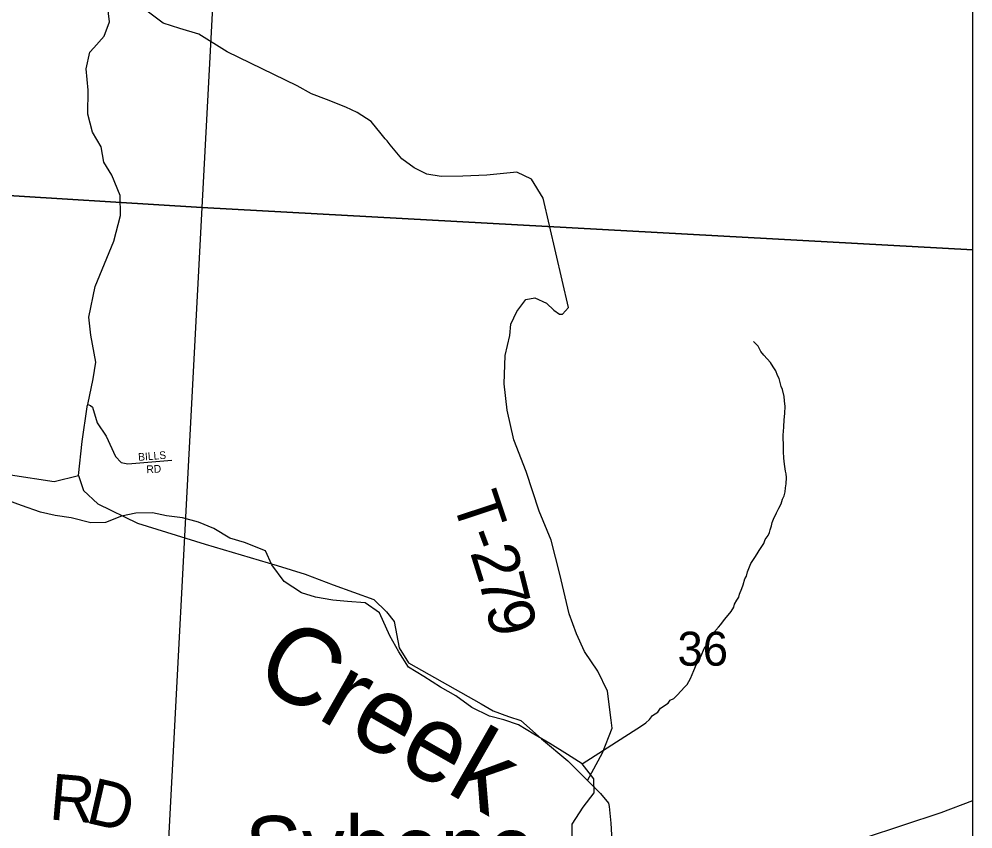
# Model space of a CAD drawing. Extents: x 1949938.81 to 1949945.61, y 152207.65 to 152214.09.
# Drawn here: x 1949944.431 to 1949945.607, y 152209.24 to 152210.239 of the extents above; entities that cross this region are included whole.
import ezdxf

# ---------------------------------------------------------------- set-up
doc = ezdxf.new("R2010")
doc.units = 0
for name, color, linetype in [('GM_X_County', 7, 'Continuous'), ('GM_X_County_Road', 7, 'Continuous'), ('GM_X_Minor_River', 7, 'Continuous'), ('GM_X_Minor_River_Text', 7, 'Continuous'), ('GM_X_Section', 7, 'Continuous'), ('GM_X_Section_Text', 7, 'Continuous'), ('GM_X_Township', 7, 'Continuous'), ('GM_X_Township_Road', 7, 'Continuous'), ('GM_X_Township_Road_Text', 7, 'Continuous'), ('GM_X_Township_ROW', 7, 'Continuous'), ('GM_X_Township_Subdivision', 7, 'Continuous'), ('GM_X_Township_Subdivision_Text', 7, 'Continuous'), ('GM_X_Unincorporated_Text', 7, 'Continuous'), ('GM_X_US_Route', 7, 'Continuous')]:
    doc.layers.add(name, color=color, linetype=linetype)

msp = doc.modelspace()

# ---------------------------------------------------------------- linework, layer by layer
at = {"layer": 'GM_X_County'}
msp.add_lwpolyline([(1949945.6069, 152208.8266), (1949945.6069, 152214.0874), (1949938.8069, 152214.0874), (1949938.8069, 152213.1813)], dxfattribs=at)
at = {"layer": 'GM_X_County_Road'}
msp.add_lwpolyline([(1949944.421, 152209.6768), (1949944.4748, 152209.6684), (1949944.5047, 152209.6757), (1949944.5108, 152209.6574), (1949944.5286, 152209.6411), (1949944.5774, 152209.6171), (1949944.6608, 152209.5912), (1949944.7494, 152209.5649), (1949944.7839, 152209.5543), (1949944.8183, 152209.5409), (1949944.8687, 152209.5231), (1949944.8843, 152209.5078), (1949944.8937, 152209.4957), (1949944.8998, 152209.4634), (1949944.9115, 152209.4451), (1949945.0009, 152209.3942), (1949945.0157, 152209.3858), (1949945.0346, 152209.3786), (1949945.0497, 152209.374), (1949945.0752, 152209.3511), (1949945.1076, 152209.3242), (1949945.1318, 152209.2997), (1949945.148, 152209.2838), (1949945.1578, 152209.2717), (1949945.1585, 152209.2678), (1949945.1608, 152209.2471), (1949945.1655, 152209.1604)], dxfattribs=at)
at = {"layer": 'GM_X_Minor_River'}
for points in [[(1949945.1253, 152209.3203), (1949945.1985, 152209.3674), (1949945.2039, 152209.3708), (1949945.2081, 152209.3749), (1949945.212, 152209.3801), (1949945.2185, 152209.3842), (1949945.222, 152209.3891), (1949945.2312, 152209.395), (1949945.2339, 152209.3987), (1949945.2381, 152209.401), (1949945.2424, 152209.4051), (1949945.2474, 152209.4103), (1949945.2516, 152209.4148), (1949945.2547, 152209.4182), (1949945.259, 152209.4257), (1949945.263, 152209.4355), (1949945.2661, 152209.4434), (1949945.2697, 152209.4491), (1949945.272, 152209.4536), (1949945.2756, 152209.4626), (1949945.2787, 152209.4664), (1949945.2822, 152209.4747), (1949945.2869, 152209.4796), (1949945.29, 152209.4852), (1949945.2935, 152209.489), (1949945.2962, 152209.4923), (1949945.3008, 152209.4983), (1949945.3051, 152209.5036), (1949945.3089, 152209.5081), (1949945.3121, 152209.5137), (1949945.3129, 152209.5171), (1949945.316, 152209.522), (1949945.3183, 152209.5258), (1949945.3192, 152209.5296), (1949945.3219, 152209.5364), (1949945.3239, 152209.5413), (1949945.3259, 152209.5485), (1949945.3279, 152209.5518), (1949945.3291, 152209.5571), (1949945.3331, 152209.5673), (1949945.3358, 152209.5711), (1949945.3381, 152209.5749), (1949945.3409, 152209.5794), (1949945.3436, 152209.5835), (1949945.3459, 152209.5873), (1949945.349, 152209.5922), (1949945.351, 152209.5971), (1949945.3545, 152209.602), (1949945.3561, 152209.6057), (1949945.3569, 152209.6091), (1949945.3585, 152209.6137), (1949945.3593, 152209.6178), (1949945.3613, 152209.622), (1949945.3649, 152209.6299), (1949945.3676, 152209.6356), (1949945.3704, 152209.6408), (1949945.3724, 152209.6469), (1949945.3743, 152209.6507), (1949945.3755, 152209.6556), (1949945.376, 152209.6605), (1949945.3768, 152209.6655), (1949945.377, 152209.6734), (1949945.3767, 152209.678), (1949945.376, 152209.6814), (1949945.3746, 152209.6898), (1949945.374, 152209.6974), (1949945.3734, 152209.7054), (1949945.3735, 152209.7142), (1949945.3729, 152209.7218), (1949945.373, 152209.7264), (1949945.3734, 152209.7298), (1949945.3739, 152209.7362), (1949945.3744, 152209.7442), (1949945.375, 152209.7529), (1949945.3755, 152209.7609), (1949945.3748, 152209.7678), (1949945.3742, 152209.7735), (1949945.3724, 152209.7819), (1949945.3706, 152209.7857), (1949945.3681, 152209.7957), (1949945.3659, 152209.7991), (1949945.3641, 152209.8049), (1949945.3608, 152209.8099), (1949945.3575, 152209.8152), (1949945.3534, 152209.8199), (1949945.3493, 152209.8241), (1949945.3456, 152209.8288), (1949945.3423, 152209.8353)], [(1949945.3423, 152209.8353), (1949945.3363, 152209.8411)], [(1949945.1129, 152209.2284), (1949945.1129, 152209.2459), (1949945.1266, 152209.2671), (1949945.1403, 152209.2845), (1949945.1397, 152209.302), (1949945.1253, 152209.3203), (1949945.1072, 152209.3317), (1949945.0853, 152209.3455), (1949945.0657, 152209.3569), (1949945.0468, 152209.3684), (1949945.0286, 152209.3746), (1949945.0112, 152209.3792), (1949944.9893, 152209.3899), (1949944.9697, 152209.4044), (1949944.9508, 152209.4151), (1949944.9304, 152209.4281), (1949944.9115, 152209.4396), (1949944.8995, 152209.4586), (1949944.8882, 152209.4784), (1949944.8754, 152209.5066), (1949944.8581, 152209.5188), (1949944.8361, 152209.5204), (1949944.8179, 152209.522), (1949944.7967, 152209.5259), (1949944.7793, 152209.5313), (1949944.7582, 152209.545), (1949944.7431, 152209.5656), (1949944.7349, 152209.5831), (1949944.7092, 152209.5931), (1949944.691, 152209.5985), (1949944.6714, 152209.6107), (1949944.6525, 152209.6184), (1949944.6328, 152209.6238), (1949944.6131, 152209.6261), (1949944.5957, 152209.63), (1949944.5752, 152209.6293), (1949944.5578, 152209.6256), (1949944.5381, 152209.6181), (1949944.5199, 152209.6174), (1949944.4957, 152209.6235), (1949944.476, 152209.6267), (1949944.4579, 152209.6305), (1949944.4344, 152209.639), (1949944.4155, 152209.6459)]]:
    msp.add_lwpolyline(points, dxfattribs=at)
at = {"layer": 'GM_X_Section'}
for p, q in [((1949945.6069, 152209.9543), (1949945.6069, 152210.9665)), ((1949945.6069, 152208.9511), (1949945.6069, 152209.9543))]:
    msp.add_line(p, q, dxfattribs=at)
for points in [[(1949944.7104, 152211.0185), (1949944.6567, 152210.0065), (1949943.5439, 152210.0754), (1949943.6063, 152211.0859)], [(1949943.5439, 152210.0754), (1949944.6567, 152210.0065), (1949944.6037, 152209.0009), (1949943.4815, 152209.0627)]]:
    msp.add_lwpolyline(points, close=True, dxfattribs=at)
for points in [[(1949945.6069, 152210.9665), (1949944.7104, 152211.0185), (1949944.6567, 152210.0065), (1949945.6069, 152209.9543)], [(1949945.6069, 152209.9543), (1949944.6567, 152210.0065), (1949944.6037, 152209.0009), (1949945.6069, 152208.9511)]]:
    msp.add_lwpolyline(points, dxfattribs=at)
at = {"layer": 'GM_X_Township'}
msp.add_lwpolyline([(1949945.6069, 152208.8266), (1949945.6069, 152214.0874), (1949942.6839, 152214.0874)], dxfattribs=at)
at = {"layer": 'GM_X_Township_Road'}
for points in [[(1949944.5236, 152210.2032), (1949944.5237, 152210.2034), (1949944.5361, 152210.2175), (1949944.543, 152210.2353), (1949944.5403, 152210.2559), (1949944.5215, 152210.2984), (1949944.5147, 152210.3164), (1949944.5145, 152210.3167)], [(1949944.5047, 152209.6757), (1949944.5093, 152209.7178), (1949944.5153, 152209.7604), (1949944.5155, 152209.7613), (1949944.516, 152209.7633), (1949944.5229, 152209.795), (1949944.5259, 152209.8155), (1949944.5199, 152209.849), (1949944.5172, 152209.871), (1949944.5252, 152209.909), (1949944.5483, 152209.9649), (1949944.5566, 152209.9965), (1949944.5562, 152210.0212), (1949944.5456, 152210.0463), (1949944.5358, 152210.0623), (1949944.5324, 152210.0813), (1949944.5221, 152210.0992), (1949944.5161, 152210.1216), (1949944.5164, 152210.1509), (1949944.5142, 152210.1772), (1949944.5187, 152210.1977), (1949944.5236, 152210.2032)], [(1949945.1318, 152209.2997), (1949945.1505, 152209.3341), (1949945.1623, 152209.3645), (1949945.161, 152209.3744), (1949945.1566, 152209.4101), (1949945.1448, 152209.4348), (1949945.1282, 152209.4591), (1949945.1183, 152209.4807), (1949945.1093, 152209.5054), (1949945.0979, 152209.5541), (1949945.0873, 152209.5963), (1949945.0725, 152209.632), (1949945.0562, 152209.681), (1949945.0411, 152209.7198), (1949945.0327, 152209.7563), (1949945.0293, 152209.789), (1949945.0305, 152209.824), (1949945.0362, 152209.8487), (1949945.0373, 152209.8624), (1949945.0449, 152209.8783), (1949945.0558, 152209.8928), (1949945.0672, 152209.8951), (1949945.0812, 152209.8882), (1949945.0903, 152209.8798), (1949945.0975, 152209.8749), (1949945.1009, 152209.8749), (1949945.1085, 152209.8829), (1949945.0771, 152210.0179), (1949945.0627, 152210.0411), (1949945.0449, 152210.0498), (1949945.0077, 152210.0464), (1949944.9782, 152210.0449), (1949944.9517, 152210.0446), (1949944.9339, 152210.0476), (1949944.9183, 152210.0552), (1949944.9032, 152210.0663), (1949944.8888, 152210.0838), (1949944.8849, 152210.0885), (1949944.8827, 152210.0912)]]:
    msp.add_lwpolyline(points, dxfattribs=at)
at = {"layer": 'GM_X_Township_ROW'}
msp.add_lwpolyline([(1949944.8827, 152210.0912), (1949944.8778, 152210.0971), (1949944.8653, 152210.1123), (1949944.8479, 152210.1234), (1949944.8339, 152210.1302), (1949944.8104, 152210.1397), (1949944.7918, 152210.1466), (1949944.774, 152210.1565), (1949944.688, 152210.1984), (1949944.6528, 152210.2201), (1949944.6297, 152210.2269), (1949944.6089, 152210.2338), (1949944.5861, 152210.2509)], dxfattribs=at)
at = {"layer": 'GM_X_Township_Subdivision'}
msp.add_lwpolyline([(1949944.516, 152209.7633), (1949944.5193, 152209.7623), (1949944.5217, 152209.7601), (1949944.5276, 152209.7407), (1949944.5386, 152209.7243), (1949944.5502, 152209.6994), (1949944.5571, 152209.6921), (1949944.5654, 152209.6903), (1949944.6197, 152209.695)], dxfattribs=at)
at = {"layer": 'GM_X_US_Route'}
msp.add_lwpolyline([(1949944.7057, 152208.9311), (1949944.7506, 152208.9526), (1949944.8652, 152209.0081), (1949944.9628, 152209.056), (1949945.0397, 152209.0871), (1949945.1044, 152209.114), (1949945.1689, 152209.1346), (1949945.2497, 152209.1595), (1949945.3096, 152209.1786), (1949945.3787, 152209.1981), (1949945.5679, 152209.2604), (1949945.6069, 152209.275)], dxfattribs=at)

# ---------------------------------------------------------------- texts
at = {"layer": 'GM_X_Minor_River_Text'}
msp.add_text('Creek', height=0.09471, rotation=330.2117, dxfattribs=at).set_placement((1949944.7175, 152209.4229))
at = {"layer": 'GM_X_Section_Text'}
msp.add_text('36', height=0.04186, rotation=0, dxfattribs=at).set_placement((1949945.2428, 152209.4414))
at = {"layer": 'GM_X_Township_Road_Text'}
for s, rotation, p in [('T', 288.3367, (1949944.9649, 152209.6448)), ('-', 290.4631, (1949944.979, 152209.6023)), ('2', 287.3429, (1949944.9869, 152209.5812)), ('7', 283.9807, (1949944.9971, 152209.5486)), ('9', 284.5034, (1949945.0057, 152209.5141)), ('R', 355.0227, (1949944.4676, 152209.252)), ('D', 347.0139, (1949944.512, 152209.2483))]:
    msp.add_text(s, height=0.0568, rotation=rotation, dxfattribs=at).set_placement(p)
at = {"layer": 'GM_X_Township_Subdivision_Text'}
for s, rotation, p in [('BILLS', 4.3986, (1949944.5785, 152209.6939)), ('RD', 3.0124, (1949944.5885, 152209.6787))]:
    msp.add_text(s, height=0.00947, rotation=rotation, dxfattribs=at).set_placement(p)
at = {"layer": 'GM_X_Unincorporated_Text'}
msp.add_text('Sybene', height=0.07898, rotation=0, dxfattribs=at).set_placement((1949944.7095, 152209.1771))

doc.saveas('drawing.dxf')
